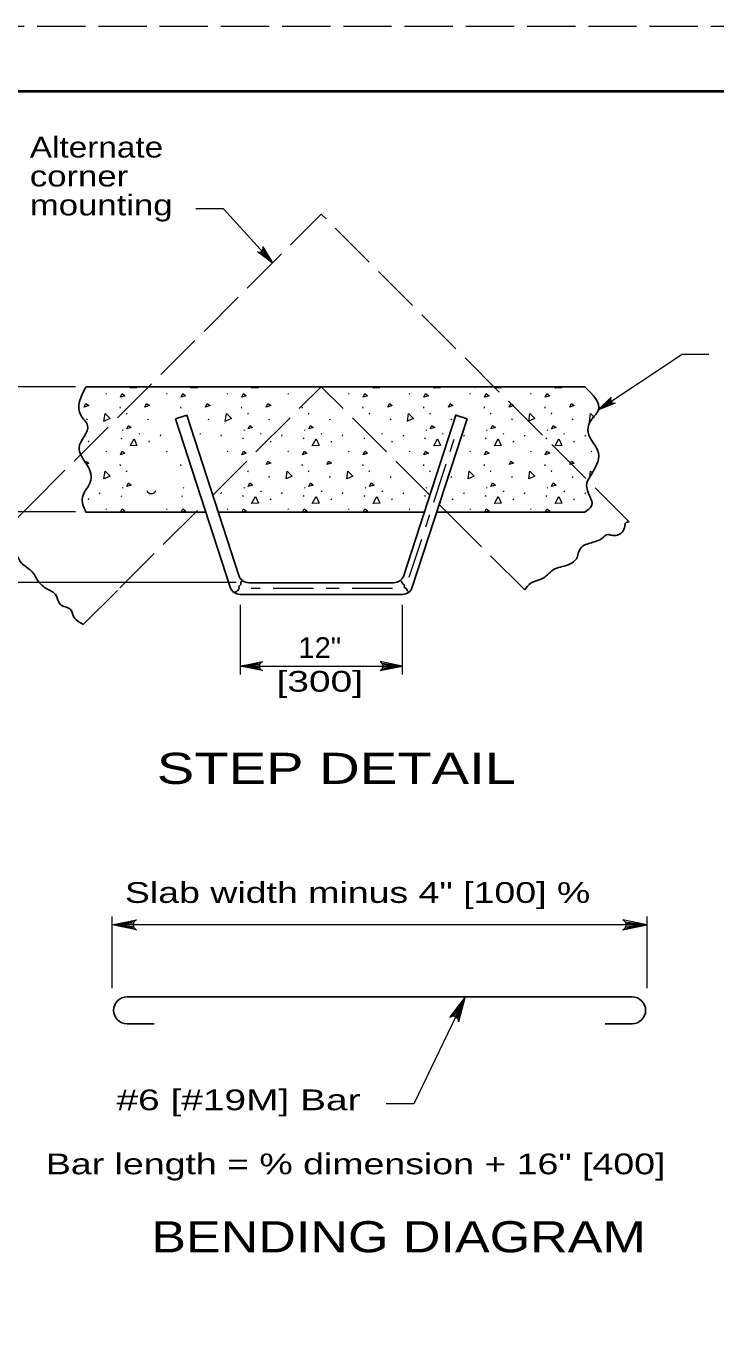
# Model space of a CAD drawing. Extents: x 1073.4 to 1107.4, y 719.4 to 741.4.
# Drawn here: x 1084.72 to 1090.03, y 731.19 to 741.35 of the extents above; entities that cross this region are included whole.
import ezdxf
from ezdxf.enums import TextEntityAlignment as Align

# ---------------------------------------------------------------- set-up
doc = ezdxf.new("R2010")
doc.units = 0
doc.header["$LTSCALE"] = 0.062
doc.linetypes.add('DOT_DASHED', pattern=[7.7, 5, -1.2, 0.3, -1.2])
doc.linetypes.add('LONG_DASHED', pattern=[7.5, 6, -1.5])
doc.layers.add('1', color=7, linetype='Continuous', lineweight=13)

msp = doc.modelspace()

# ---------------------------------------------------------------- linework, layer by layer
at = {"layer": '1', "lineweight": 25}
for p, q in [((1075.36142, 740.85408), (1106.86142, 740.85408)), ((1085.18067, 738.575), (1089.02608, 738.575)), ((1085.87133, 738.32675), (1085.95758, 738.35475)), ((1086.29333, 737.02842), (1085.87133, 738.32675)), ((1086.35917, 737.11908), (1085.95758, 738.35475)), ((1087.63033, 737.11908), (1088.032, 738.35475)), ((1087.69625, 737.02842), (1088.11817, 738.32675)), ((1088.032, 738.35475), (1088.11817, 738.32675)), ((1086.10508, 737.60767), (1085.18067, 737.60767)), ((1087.78917, 737.60767), (1086.20042, 737.60767)), ((1089.02608, 737.60767), (1087.88442, 737.60767)), ((1086.43592, 737.06342), (1087.55367, 737.06342)), ((1086.37, 736.97267), (1087.61958, 736.97267)), ((1085.49892, 733.86983), (1089.39033, 733.86983)), ((1085.707, 733.66117), (1085.49892, 733.66117)), ((1089.18225, 733.66117), (1089.39033, 733.66117))]:
    msp.add_line(p, q, dxfattribs=at)
at = {"layer": '1'}
for p, q in [((1086.24267, 739.94717), (1086.02925, 739.94717)), ((1086.57775, 739.57533), (1086.24267, 739.94717)), ((1086.53675, 739.62033), (1086.61875, 739.52933)), ((1086.54383, 739.62967), (1086.61875, 739.52933)), ((1086.54667, 739.639), (1086.61875, 739.52933)), ((1086.51967, 739.61258), (1086.61875, 739.52933)), ((1086.52917, 739.61525), (1086.61875, 739.52933)), ((1089.127, 738.39275), (1089.77775, 738.82458)), ((1089.77775, 738.82458), (1089.98192, 738.82458)), ((1085.1, 738.575), (1083.743, 738.575)), ((1085.33425, 738.52267), (1085.3385, 738.51633)), ((1085.52275, 738.5625), (1085.52942, 738.575)), ((1085.802, 738.52267), (1085.80633, 738.51633)), ((1085.99058, 738.5625), (1085.99717, 738.575)), ((1086.26975, 738.52267), (1086.274, 738.51633)), ((1086.45833, 738.5625), (1086.465, 738.575)), ((1086.73758, 738.52267), (1086.74183, 738.51633)), ((1087.20533, 738.52267), (1087.20958, 738.51633)), ((1087.39383, 738.5625), (1087.4005, 738.575)), ((1087.67308, 738.52267), (1087.67733, 738.51633)), ((1087.86167, 738.5625), (1087.86833, 738.575)), ((1088.14083, 738.52267), (1088.14525, 738.51633)), ((1088.32942, 738.5625), (1088.336, 738.575)), ((1088.60867, 738.52267), (1088.61292, 738.51633)), ((1088.79717, 738.5625), (1088.80383, 738.575)), ((1085.44283, 738.41967), (1085.44392, 738.41008)), ((1085.91058, 738.41967), (1085.91167, 738.41008)), ((1086.37833, 738.41967), (1086.37942, 738.41008)), ((1086.84608, 738.41967), (1086.84725, 738.41008)), ((1087.31392, 738.41967), (1087.315, 738.41008)), ((1087.78167, 738.41967), (1087.78275, 738.41008)), ((1088.24942, 738.41967), (1088.2505, 738.41008)), ((1088.71717, 738.41967), (1088.71833, 738.41008)), ((1089.22383, 738.47858), (1089.127, 738.39275)), ((1089.22517, 738.46875), (1089.127, 738.39275)), ((1089.229, 738.4605), (1089.127, 738.39275)), ((1089.23733, 738.45217), (1089.127, 738.39275)), ((1089.246, 738.448), (1089.127, 738.39275)), ((1085.18933, 738.31867), (1085.19358, 738.32833)), ((1085.49383, 738.36275), (1085.49808, 738.37242)), ((1085.657, 738.31867), (1085.66133, 738.32833)), ((1086.12483, 738.31867), (1086.12908, 738.32833)), ((1086.42933, 738.36275), (1086.43367, 738.37242)), ((1086.59258, 738.31867), (1086.59692, 738.32833)), ((1086.89708, 738.36275), (1086.90142, 738.37242)), ((1087.06033, 738.31867), (1087.06467, 738.32833)), ((1087.36492, 738.36275), (1087.36917, 738.37242)), ((1087.52808, 738.31867), (1087.53242, 738.32833)), ((1087.83267, 738.36275), (1087.837, 738.37242)), ((1087.99592, 738.31867), (1088.00017, 738.32833)), ((1088.03567, 738.35358), (1088.03458, 738.3595)), ((1088.30042, 738.36275), (1088.30467, 738.37242)), ((1088.46367, 738.31867), (1088.468, 738.32833)), ((1088.76825, 738.36275), (1088.7725, 738.37242)), ((1088.93142, 738.31867), (1088.93567, 738.32833)), ((1089.07733, 738.31458), (1089.06308, 738.308)), ((1085.287, 738.19408), (1085.29133, 738.20375)), ((1085.46267, 738.2425), (1085.467, 738.236)), ((1085.59133, 738.21517), (1085.59567, 738.20867)), ((1085.75467, 738.19408), (1085.75908, 738.20375)), ((1086.05908, 738.21517), (1086.06333, 738.20867)), ((1086.2225, 738.19408), (1086.22683, 738.20375)), ((1086.39825, 738.2425), (1086.4025, 738.236)), ((1086.52692, 738.21517), (1086.53117, 738.20867)), ((1086.69025, 738.19408), (1086.69467, 738.20375)), ((1086.866, 738.2425), (1086.87033, 738.236)), ((1086.99467, 738.21517), (1086.99892, 738.20867)), ((1087.15808, 738.19408), (1087.16233, 738.20375)), ((1087.46242, 738.21517), (1087.46667, 738.20867)), ((1087.62592, 738.19408), (1087.63017, 738.20375)), ((1087.8015, 738.2425), (1087.80583, 738.236)), ((1087.93017, 738.21517), (1087.9345, 738.20867)), ((1088.09367, 738.19408), (1088.09792, 738.20375)), ((1088.26933, 738.2425), (1088.27358, 738.236)), ((1088.398, 738.21517), (1088.40225, 738.20867)), ((1088.56142, 738.19408), (1088.56567, 738.20375)), ((1088.73708, 738.2425), (1088.74133, 738.236)), ((1088.86567, 738.21517), (1088.87, 738.20867)), ((1089.02917, 738.19408), (1089.0335, 738.20375)), ((1085.2, 738.147), (1085.20433, 738.15667)), ((1085.45458, 738.17167), (1085.45883, 738.18133)), ((1085.66767, 738.147), (1085.67208, 738.15667)), ((1086.39008, 738.17167), (1086.39433, 738.18133)), ((1086.60333, 738.147), (1086.60767, 738.15667)), ((1086.85783, 738.17167), (1086.86217, 738.18133)), ((1087.07108, 738.147), (1087.07533, 738.15667)), ((1087.32567, 738.17167), (1087.32992, 738.18133)), ((1087.53892, 738.147), (1087.54317, 738.15667)), ((1087.79342, 738.17167), (1087.79767, 738.18133)), ((1088.26117, 738.17167), (1088.26542, 738.18133)), ((1088.47442, 738.147), (1088.47867, 738.15667)), ((1088.729, 738.17167), (1088.73325, 738.18133)), ((1088.94217, 738.147), (1088.9465, 738.15667)), ((1085.33425, 738.07825), (1085.3385, 738.07183)), ((1085.802, 738.07825), (1085.80633, 738.07183)), ((1086.26975, 738.07825), (1086.274, 738.07183)), ((1086.73758, 738.07825), (1086.74183, 738.07183)), ((1087.20533, 738.07825), (1087.20958, 738.07183)), ((1087.67308, 738.07825), (1087.67733, 738.07183)), ((1088.14083, 738.07825), (1088.14525, 738.07183)), ((1088.60867, 738.07825), (1088.61292, 738.07183)), ((1089.07633, 738.07825), (1089.08075, 738.07183)), ((1085.44283, 737.97533), (1085.44392, 737.96567)), ((1085.49383, 737.91833), (1085.49808, 737.928)), ((1085.91058, 737.97533), (1085.91167, 737.96567)), ((1086.42933, 737.91833), (1086.43367, 737.928)), ((1086.84608, 737.97533), (1086.84725, 737.96567)), ((1086.89708, 737.91833), (1086.90142, 737.928)), ((1087.31392, 737.97533), (1087.315, 737.96567)), ((1087.36492, 737.91833), (1087.36917, 737.928)), ((1087.78167, 737.97533), (1087.78275, 737.96567)), ((1087.83267, 737.91833), (1087.837, 737.928)), ((1088.24942, 737.97533), (1088.2505, 737.96567)), ((1088.30042, 737.91833), (1088.30467, 737.928)), ((1088.71717, 737.97533), (1088.71833, 737.96567)), ((1088.76825, 737.91833), (1088.7725, 737.928)), ((1085.46267, 737.798), (1085.467, 737.79158)), ((1085.93042, 737.798), (1085.93475, 737.79158)), ((1086.39825, 737.798), (1086.4025, 737.79158)), ((1086.59258, 737.87425), (1086.59692, 737.88392)), ((1086.866, 737.798), (1086.87033, 737.79158)), ((1087.06033, 737.87425), (1087.06467, 737.88392)), ((1087.33375, 737.798), (1087.338, 737.79158)), ((1087.52808, 737.87425), (1087.53242, 737.88392)), ((1087.8015, 737.798), (1087.80583, 737.79158)), ((1087.99592, 737.87425), (1088.00017, 737.88392)), ((1088.26933, 737.798), (1088.27358, 737.79158)), ((1088.46367, 737.87425), (1088.468, 737.88392)), ((1088.73708, 737.798), (1088.74133, 737.79158)), ((1088.93142, 737.87425), (1088.93567, 737.88392)), ((1085.2, 737.70258), (1085.20433, 737.71225)), ((1085.287, 737.74967), (1085.29133, 737.75933)), ((1085.45458, 737.72725), (1085.45883, 737.73692)), ((1085.92233, 737.72725), (1085.92667, 737.73692)), ((1086.2225, 737.74967), (1086.22683, 737.75933)), ((1086.39008, 737.72725), (1086.39433, 737.73692)), ((1086.52692, 737.77067), (1086.53117, 737.76425)), ((1086.60333, 737.70258), (1086.60767, 737.71225)), ((1086.69025, 737.74967), (1086.69467, 737.75933)), ((1086.85783, 737.72725), (1086.86217, 737.73692)), ((1086.99467, 737.77067), (1086.99892, 737.76425)), ((1087.07108, 737.70258), (1087.07533, 737.71225)), ((1087.15808, 737.74967), (1087.16233, 737.75933)), ((1087.32567, 737.72725), (1087.32992, 737.73692)), ((1087.46242, 737.77067), (1087.46667, 737.76425)), ((1087.53892, 737.70258), (1087.54317, 737.71225)), ((1087.62592, 737.74967), (1087.63017, 737.75933)), ((1087.79342, 737.72725), (1087.79767, 737.73692)), ((1088.00667, 737.70258), (1088.011, 737.71225)), ((1088.09367, 737.74967), (1088.09792, 737.75933)), ((1088.26117, 737.72725), (1088.26542, 737.73692)), ((1088.398, 737.77067), (1088.40225, 737.76425)), ((1088.47442, 737.70258), (1088.47867, 737.71225)), ((1088.56142, 737.74967), (1088.56567, 737.75933)), ((1088.729, 737.72725), (1088.73325, 737.73692)), ((1088.86567, 737.77067), (1088.87, 737.76425)), ((1088.94217, 737.70258), (1088.9465, 737.71225)), ((1089.02917, 737.74967), (1089.0335, 737.75933)), ((1085.09975, 737.60867), (1083.74275, 737.60867)), ((1085.33425, 737.63383), (1085.3385, 737.62733)), ((1085.802, 737.63383), (1085.80633, 737.62733)), ((1086.26975, 737.63383), (1086.274, 737.62733)), ((1086.73758, 737.63383), (1086.74183, 737.62733)), ((1087.20533, 737.63383), (1087.20958, 737.62733)), ((1087.67308, 737.63383), (1087.67733, 737.62733)), ((1087.78667, 737.60767), (1087.79433, 737.6235)), ((1088.14083, 737.63383), (1088.14525, 737.62733)), ((1088.60867, 737.63383), (1088.61292, 737.62733)), ((1086.34033, 737.065), (1083.74267, 737.065)), ((1086.37, 736.89208), (1086.37, 736.35567)), ((1087.61958, 736.89208), (1087.61958, 736.35567)), ((1086.52508, 736.442), (1086.37, 736.42025)), ((1086.51983, 736.43125), (1086.37, 736.42025)), ((1086.51825, 736.42025), (1086.37, 736.42025)), ((1086.521, 736.40633), (1086.37, 736.42025)), ((1086.527, 736.39633), (1086.37, 736.42025)), ((1087.46267, 736.39633), (1087.61958, 736.42025)), ((1087.4645, 736.442), (1087.61958, 736.42025)), ((1087.46858, 736.40633), (1087.61958, 736.42025)), ((1087.46967, 736.43125), (1087.61958, 736.42025)), ((1087.47133, 736.42025), (1087.61958, 736.42025)), ((1085.3825, 733.93733), (1085.3825, 734.48783)), ((1085.55317, 734.44875), (1085.3825, 734.42492)), ((1085.54733, 734.437), (1085.3825, 734.42492)), ((1089.33625, 734.44875), (1089.50683, 734.42492)), ((1089.34192, 734.43692), (1089.50683, 734.42492)), ((1089.50683, 733.93733), (1089.50683, 734.48783)), ((1089.50683, 734.42492), (1085.3825, 734.42492)), ((1085.54558, 734.42492), (1085.3825, 734.42492)), ((1085.54858, 734.40958), (1085.3825, 734.42492)), ((1085.55517, 734.3985), (1085.3825, 734.42492)), ((1089.33425, 734.3985), (1089.50683, 734.42492)), ((1089.34075, 734.40958), (1089.50683, 734.42492)), ((1089.34375, 734.42492), (1089.50683, 734.42492)), ((1088.00275, 733.71867), (1088.10225, 733.86208)), ((1088.01558, 733.71967), (1088.10225, 733.86208)), ((1088.03058, 733.71567), (1088.10225, 733.86208)), ((1088.04067, 733.70867), (1088.10225, 733.86208)), ((1088.04875, 733.69833), (1088.10225, 733.86208))]:
    msp.add_line(p, q, dxfattribs=at)
at = {"layer": '1', "linetype": 'LONG_DASHED', "lineweight": 25}
for p, q in [((1089.36783, 737.53242), (1086.99475, 739.90533)), ((1086.158, 737.73833), (1086.99475, 738.575)), ((1087.83167, 737.73833), (1086.99475, 738.575)), ((1085.44375, 737.02425), (1086.086, 737.66633)), ((1088.563, 737.007), (1087.90358, 737.66633)), ((1085.1605, 736.741), (1085.44375, 737.02425))]:
    msp.add_line(p, q, dxfattribs=at)
at = {"layer": '1', "linetype": 'DOT_DASHED'}
for p, q in [((1087.67342, 737.10517), (1088.04742, 738.25592)), ((1087.544, 737.01833), (1086.45492, 737.01833))]:
    msp.add_line(p, q, dxfattribs=at)
at = {"layer": '1', "linetype": 'LONG_DASHED'}
msp.add_line((1087.90358, 737.66633), (1088.03992, 737.53), dxfattribs=at)
msp.add_lwpolyline([(1073.36142, 719.35408), (1107.36142, 719.35408), (1107.36142, 741.35408), (1073.36142, 741.35408)], close=True, dxfattribs=at)
at = {"layer": '1', "lineweight": 40}
msp.add_lwpolyline([(1075.36142, 740.85408), (1106.86142, 740.85408), (1106.86142, 719.85408), (1075.36142, 719.85408)], close=True, dxfattribs=at)
msp.add_lwpolyline([(1075.36142, 740.85408), (1106.86142, 740.85408), (1106.86142, 719.85408), (1075.36142, 719.85408)], close=True, dxfattribs=at)
at = {"layer": '1', "linetype": 'LONG_DASHED', "lineweight": 25}
msp.add_lwpolyline([(1084.49533, 737.406), (1084.75617, 737.66692), (1086.99475, 739.90533)], dxfattribs=at)
at = {"layer": '1'}
for points in [[(1086.545, 739.65342), (1086.61875, 739.52933), (1086.503, 739.61558)], [(1085.57067, 738.575), (1085.57433, 738.56675), (1085.52392, 738.5625)], [(1086.03833, 738.575), (1086.04208, 738.56675), (1085.99167, 738.5625)], [(1086.50617, 738.575), (1086.50992, 738.56675), (1086.45942, 738.5625)], [(1087.44167, 738.575), (1087.44542, 738.56675), (1087.395, 738.5625)], [(1087.90942, 738.575), (1087.91317, 738.56675), (1087.86267, 738.5625)], [(1088.15642, 738.575), (1088.1695, 738.57333), (1088.18, 738.568)], [(1088.37725, 738.575), (1088.381, 738.56675), (1088.3305, 738.5625)], [(1088.845, 738.575), (1088.84867, 738.56675), (1088.79825, 738.5625)], [(1089.26067, 738.44742), (1089.127, 738.39275), (1089.22933, 738.49467)], [(1085.31992, 738.30767), (1085.32842, 738.369), (1085.36692, 738.32925), (1085.321, 738.308)], [(1086.25542, 738.30767), (1086.264, 738.369), (1086.30242, 738.32925), (1086.2565, 738.308)], [(1087.65875, 738.30767), (1087.66733, 738.369), (1087.70575, 738.32925), (1087.65975, 738.308)], [(1088.59433, 738.30767), (1088.60283, 738.369), (1088.64133, 738.32925), (1088.59533, 738.308)], [(1089.06208, 738.30767), (1089.07058, 738.369), (1089.10025, 738.33833)], [(1085.52275, 738.118), (1085.55175, 738.17275), (1085.57433, 738.12233), (1085.52392, 738.118)], [(1086.92608, 738.118), (1086.95508, 738.17275), (1086.97767, 738.12233), (1086.92717, 738.118)], [(1087.86167, 738.118), (1087.89067, 738.17275), (1087.91317, 738.12233), (1087.86267, 738.118)], [(1088.32942, 738.118), (1088.35833, 738.17275), (1088.381, 738.12233), (1088.3305, 738.118)], [(1088.79717, 738.118), (1088.82617, 738.17275), (1088.84867, 738.12233), (1088.79825, 738.118)], [(1085.17733, 737.99308), (1085.18092, 738.0005), (1085.20233, 737.98433), (1085.18325, 737.97833)], [(1085.31992, 737.86317), (1085.32842, 737.9245), (1085.36692, 737.88475), (1085.321, 737.8635)], [(1086.72325, 737.86317), (1086.73167, 737.9245), (1086.77025, 737.88475), (1086.72425, 737.8635)], [(1087.191, 737.86317), (1087.1995, 737.9245), (1087.238, 737.88475), (1087.192, 737.8635)], [(1088.00733, 737.98558), (1088.009, 737.98433), (1088.00667, 737.98367)], [(1088.12658, 737.86317), (1088.135, 737.9245), (1088.1735, 737.88475), (1088.12758, 737.8635)], [(1088.59433, 737.86317), (1088.60283, 737.9245), (1088.64133, 737.88475), (1088.59533, 737.8635)], [(1089.06392, 737.87617), (1089.07058, 737.9245), (1089.07892, 737.916)], [(1086.45833, 737.67358), (1086.48733, 737.72833), (1086.50992, 737.67792), (1086.45942, 737.67358)], [(1086.92608, 737.67358), (1086.95508, 737.72833), (1086.97767, 737.67792), (1086.92717, 737.67358)], [(1087.39383, 737.67358), (1087.42283, 737.72833), (1087.44542, 737.67792), (1087.395, 737.67358)], [(1088.32942, 737.67358), (1088.35833, 737.72833), (1088.381, 737.67792), (1088.3305, 737.67358)], [(1088.79717, 737.67358), (1088.82617, 737.72833), (1088.84867, 737.67792), (1088.79825, 737.67358)], [(1085.44783, 737.60767), (1085.45983, 737.63275), (1085.48133, 737.61667), (1085.45242, 737.60767)], [(1085.91558, 737.60767), (1085.92767, 737.63275), (1085.94908, 737.61667), (1085.92017, 737.60767)], [(1086.38333, 737.60767), (1086.39542, 737.63275), (1086.41692, 737.61667), (1086.388, 737.60767)], [(1086.85108, 737.60767), (1086.86325, 737.63275), (1086.88467, 737.61667), (1086.85567, 737.60767)], [(1087.31892, 737.60767), (1087.331, 737.63275), (1087.35242, 737.61667), (1087.3235, 737.60767)], [(1087.90975, 737.6855), (1087.91317, 737.67792), (1087.90708, 737.67742)], [(1088.25442, 737.60767), (1088.26658, 737.63275), (1088.288, 737.61667), (1088.259, 737.60767)], [(1088.72217, 737.60767), (1088.73433, 737.63275), (1088.75583, 737.61667), (1088.72675, 737.60767)], [(1086.54133, 736.386), (1086.37, 736.42025), (1086.54133, 736.4545)], [(1086.37, 736.42025), (1087.24417, 736.42025), (1087.61958, 736.42025)], [(1087.44825, 736.386), (1087.61958, 736.42025), (1087.44825, 736.4545)], [(1085.57092, 734.38717), (1085.3825, 734.42492), (1085.57092, 734.46258)], [(1089.31833, 734.38717), (1089.50683, 734.42492), (1089.31833, 734.46258)], [(1088.10225, 733.86208), (1087.7095, 733.04458), (1087.49608, 733.04458)], [(1087.98558, 733.70933), (1088.10225, 733.86208), (1088.05333, 733.67625)]]:
    msp.add_lwpolyline(points, dxfattribs=at)
for points in [[(1085.447, 738.49483), (1085.45983, 738.52167), (1085.48133, 738.50558)], [(1085.91475, 738.49483), (1085.92767, 738.52167), (1085.94908, 738.50558)], [(1086.38258, 738.49483), (1086.39542, 738.52167), (1086.41692, 738.50558)], [(1087.31808, 738.49483), (1087.331, 738.52167), (1087.35242, 738.50558)], [(1087.78583, 738.49483), (1087.79875, 738.52167), (1087.82017, 738.50558)], [(1088.25367, 738.49483), (1088.26658, 738.52167), (1088.288, 738.50558)], [(1088.72133, 738.49483), (1088.73433, 738.52167), (1088.75583, 738.50558)], [(1085.168, 738.41808), (1085.18092, 738.44492), (1085.20233, 738.42883)], [(1085.63575, 738.41808), (1085.64867, 738.44492), (1085.67017, 738.42883)], [(1086.1035, 738.41808), (1086.11642, 738.44492), (1086.13792, 738.42883)], [(1086.57133, 738.41808), (1086.58417, 738.44492), (1086.60567, 738.42883)], [(1087.50683, 738.41808), (1087.51967, 738.44492), (1087.54125, 738.42883)], [(1087.97458, 738.41808), (1087.9875, 738.44492), (1088.009, 738.42883)], [(1088.44242, 738.41808), (1088.45533, 738.44492), (1088.47675, 738.42883)], [(1088.91008, 738.41808), (1088.923, 738.44492), (1088.9445, 738.42883)], [(1085.49592, 738.25), (1085.50883, 738.27683), (1085.53033, 738.26067)], [(1086.43142, 738.25), (1086.44433, 738.27683), (1086.46592, 738.26067)], [(1086.89925, 738.25), (1086.91217, 738.27683), (1086.93358, 738.26067)], [(1087.83475, 738.25), (1087.84767, 738.27683), (1087.86908, 738.26067)], [(1088.3025, 738.25), (1088.31542, 738.27683), (1088.337, 738.26067)], [(1088.77033, 738.25), (1088.78325, 738.27683), (1088.80467, 738.26067)], [(1085.447, 738.05033), (1085.45983, 738.07725), (1085.48133, 738.06108)], [(1086.38258, 738.05033), (1086.39542, 738.07725), (1086.41692, 738.06108)], [(1086.57133, 737.97367), (1086.58417, 738.0005), (1086.60567, 737.98433)], [(1086.85033, 738.05033), (1086.86325, 738.07725), (1086.88467, 738.06108)], [(1087.039, 737.97367), (1087.052, 738.0005), (1087.07342, 737.98433)], [(1087.31808, 738.05033), (1087.331, 738.07725), (1087.35242, 738.06108)], [(1087.78583, 738.05033), (1087.79875, 738.07725), (1087.82017, 738.06108)], [(1088.25367, 738.05033), (1088.26658, 738.07725), (1088.288, 738.06108)], [(1088.44242, 737.97367), (1088.45533, 738.0005), (1088.47675, 737.98433)], [(1088.72133, 738.05033), (1088.73433, 738.07725), (1088.75583, 738.06108)], [(1088.91008, 737.97367), (1088.923, 738.0005), (1088.9445, 737.98433)], [(1085.49592, 737.8055), (1085.50883, 737.83233), (1085.53033, 737.81625)], [(1086.43142, 737.8055), (1086.44433, 737.83233), (1086.46592, 737.81625)], [(1086.89925, 737.8055), (1086.91217, 737.83233), (1086.93358, 737.81625)], [(1087.367, 737.8055), (1087.37992, 737.83233), (1087.40142, 737.81625)], [(1088.3025, 737.8055), (1088.31542, 737.83233), (1088.337, 737.81625)], [(1088.77033, 737.8055), (1088.78325, 737.83233), (1088.80467, 737.81625)]]:
    msp.add_lwpolyline(points, close=True, dxfattribs=at)
at = {"layer": '1', "lineweight": 25}
for points in [[(1086.3885, 737.07883), (1086.37433, 737.06933), (1086.374, 737.05808), (1086.374, 737.04817), (1086.36142, 737.037), (1086.35975, 737.02717), (1086.36275, 737.01683), (1086.355, 737.00867), (1086.35033, 737.00133), (1086.34517, 736.99575), (1086.32258, 736.98808)], [(1087.60108, 737.07883), (1087.61267, 737.07467), (1087.61567, 737.06392), (1087.62567, 737.05233), (1087.63558, 737.04317), (1087.63483, 737.02783), (1087.65242, 737.01642), (1087.65783, 737.00183), (1087.66692, 736.99342), (1087.667, 736.98808)]]:
    msp.add_lwpolyline(points, dxfattribs=at)
at = {"layer": '1'}
for centre, radius, start, end in [((1086.51634, 739.64299), 0.03056, 244.07763, 19.90376), ((1089.25445, 738.47739), 0.03056, 145.65458, 281.48071), ((1085.68551, 737.78782), 0.03698, 202.08782, 337.91395), ((1086.55517, 736.41964), 0.03698, 112.08782, 247.91395), ((1087.43441, 736.42029), 0.03698, 292.08605, 67.91218), ((1085.58618, 734.42491), 0.04068, 112.08782, 247.91395), ((1089.30314, 734.42491), 0.04068, 292.08605, 67.91218), ((1088.01284, 733.67911), 0.04068, 356.02589, 131.85202)]:
    msp.add_arc(centre, radius, start, end, dxfattribs=at)
at = {"layer": '1', "lineweight": 25}
for centre, major_axis, start_param, end_param in [((1086.43585, 737.14404), (-0.08063, 0), 0.31378916, 1.57079633), ((1087.55373, 737.14404), (-0.08063, 0), 1.57079633, 2.82780349), ((1086.36998, 737.05334), (-0.08063, 0), 0.31438562, 1.57079633), ((1087.6196, 737.05334), (0.08063, 0), 4.71238898, 5.96879968), ((1085.49895, 733.76549), (-0.10435, 0), 4.71238898, 7.85398163), ((1089.39038, 733.76549), (0.10435, 0), 4.71238898, 7.85398163)]:
    msp.add_ellipse(centre, major_axis=major_axis, ratio=0.999895, start_param=start_param, end_param=end_param, dxfattribs=at)
for points in [[(1085.18067, 737.60767), (1085.15433, 737.72208), (1085.22017, 737.854), (1085.18067, 737.98575), (1085.128, 738.10458), (1085.19392, 738.276), (1085.14117, 738.35508), (1085.18067, 738.575)], [(1089.02608, 738.575), (1089.13133, 738.39467), (1089.06558, 738.30233), (1089.05233, 738.22325), (1089.13133, 738.065), (1089.06558, 737.88033), (1089.03925, 737.81433), (1089.07867, 737.65617), (1089.02608, 737.60767)], [(1088.563, 737.007), (1088.61208, 737.06108), (1088.69442, 737.09275), (1088.73875, 737.12442), (1088.78317, 737.1625), (1088.89717, 737.20058), (1088.96683, 737.25758), (1088.97942, 737.30192), (1089.01117, 737.34633), (1089.05542, 737.36525), (1089.09975, 737.378), (1089.15675, 737.40333), (1089.2075, 737.435), (1089.23283, 737.42867), (1089.31508, 737.454), (1089.33417, 737.49833), (1089.34042, 737.52367), (1089.36808, 737.53242)], [(1084.49533, 737.406), (1084.50567, 737.38), (1084.56033, 737.33842), (1084.60967, 737.30967), (1084.64867, 737.27333), (1084.68508, 737.21342), (1084.72142, 737.18475), (1084.776, 737.13533), (1084.80725, 737.08325), (1084.87225, 737.02075), (1084.95275, 736.9635), (1084.98142, 736.89833), (1085.06467, 736.85408), (1085.088, 736.79692), (1085.127, 736.76042), (1085.1605, 736.741)]]:
    msp.add_spline(points, degree=3, dxfattribs=at)

# ---------------------------------------------------------------- texts
at = {"layer": '1'}
for s, height, width, p in [('Alternate', 0.16, 1.2, (1084.74892, 740.34208)), ('corner', 0.16, 1.25, (1084.74892, 740.11917)), ('mounting', 0.16, 1.25, (1084.74892, 739.89625)), ('STEP DETAIL', 0.24, 1.35, (1085.72708, 735.5115)), ('Slab width minus 4" [100] %', 0.16, 1.35, (1085.48158, 734.59375)), ('#6 [#19M] Bar', 0.16, 1.4, (1085.41617, 732.99467)), ('Bar length = % dimension + 16" [400]', 0.16, 1.35, (1084.87233, 732.50067)), ('BENDING DIAGRAM', 0.24, 1.25, (1085.68467, 731.89892))]:
    msp.add_text(s, height=height, dxfattribs=dict(at, width=width)).set_placement(p)
for s, width, p in [('12"', 1.05, (1086.98325, 736.48267)), ('[300]', 1.4, (1086.98325, 736.22267))]:
    msp.add_text(s, height=0.16, dxfattribs=dict(at, width=width)).set_placement(p, align=Align.CENTER)

doc.saveas('drawing.dxf')
